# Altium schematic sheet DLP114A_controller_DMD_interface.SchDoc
size 431 x 558 mm; Date: Not shown in title block; ApprovedBy: Not shown in title block; CheckedBy: Not shown in title block; Author: Not shown in title block; CompanyName: Not shown in title block; Engineer: Not shown in title block; Organization: Not shown in title block; Address1: Not shown in title block; Address2: Not shown in title block; Address3: Not shown in title block; Address4: Not shown in title block; DocumentNumber: 7; Revision: Use project parameter SCH_Rev; SheetNumber: 7; SheetTotal: 7; PageSetup: Record=PageOptions¦CenterHorizontal=True¦CenterVertical=True¦PrintScale=1.00¦XCorrection=1.00¦YCorrection=1.00¦PrintKind=0¦BorderSize=5000000¦LeftOffset=0¦BottomOffset=0¦Orientation=2¦PaperLength=1000¦PaperWidth=1000¦Scale=100¦PaperSource=15¦PrintQuality=600¦MediaType=1¦DitherType=10¦PaperKind=Letter¦PrintScaleMode=1
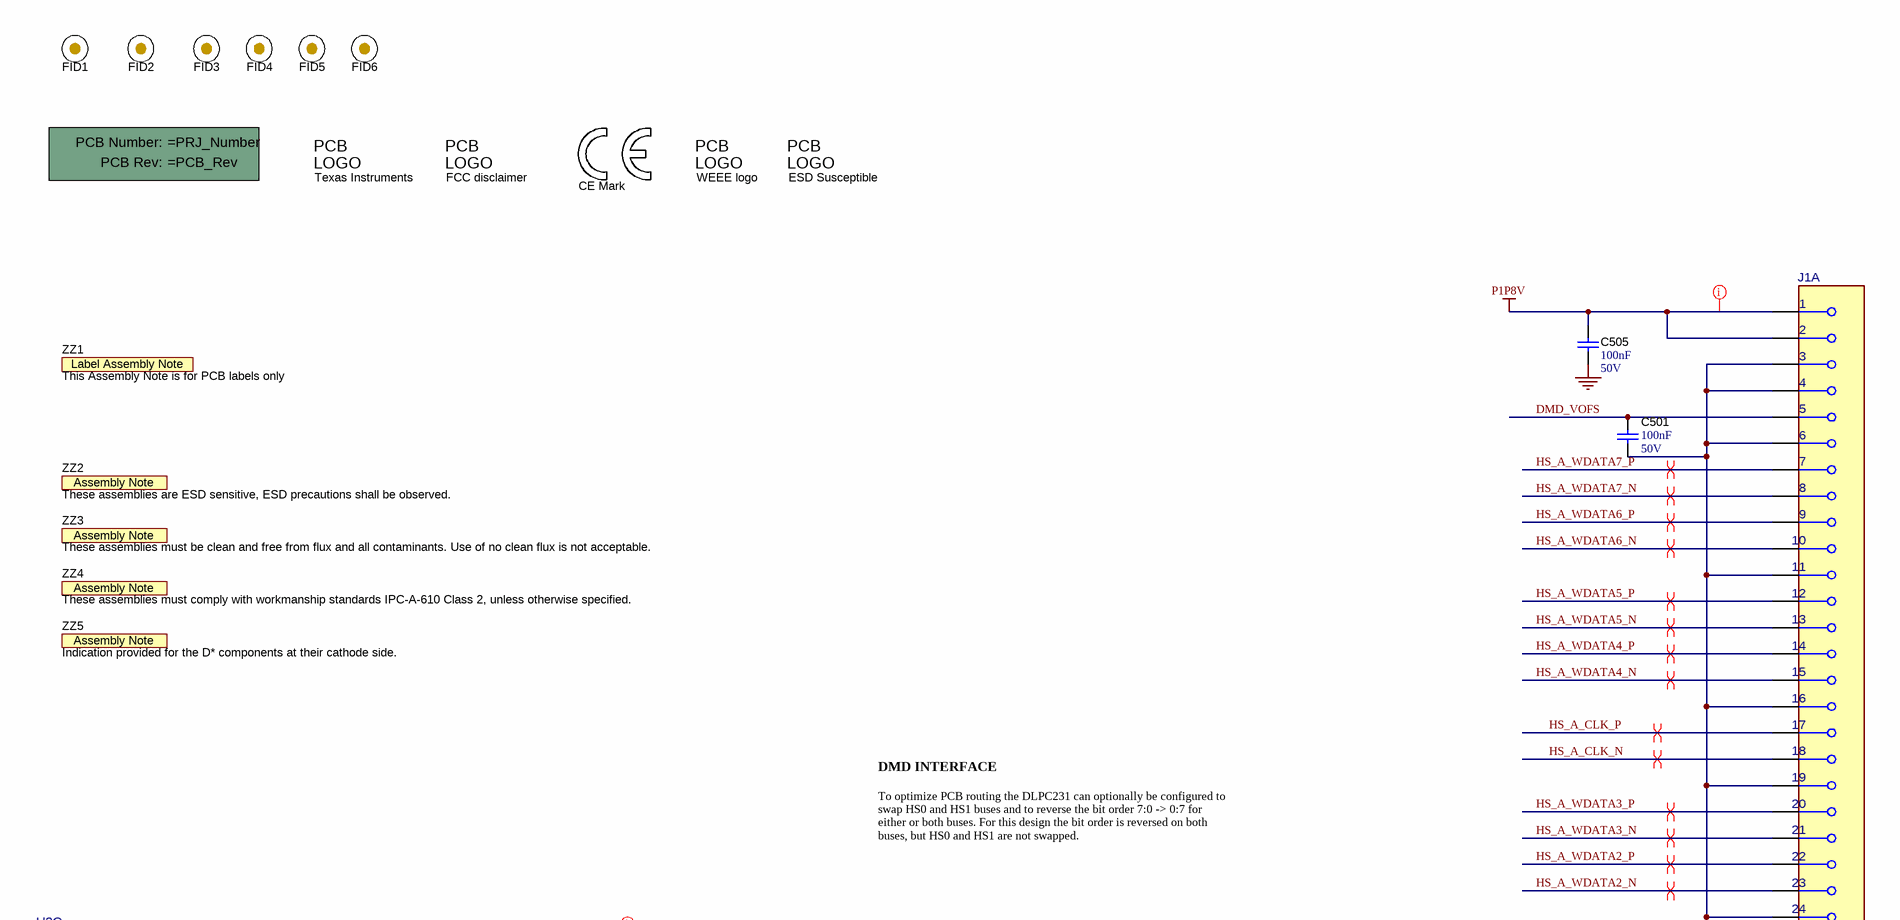
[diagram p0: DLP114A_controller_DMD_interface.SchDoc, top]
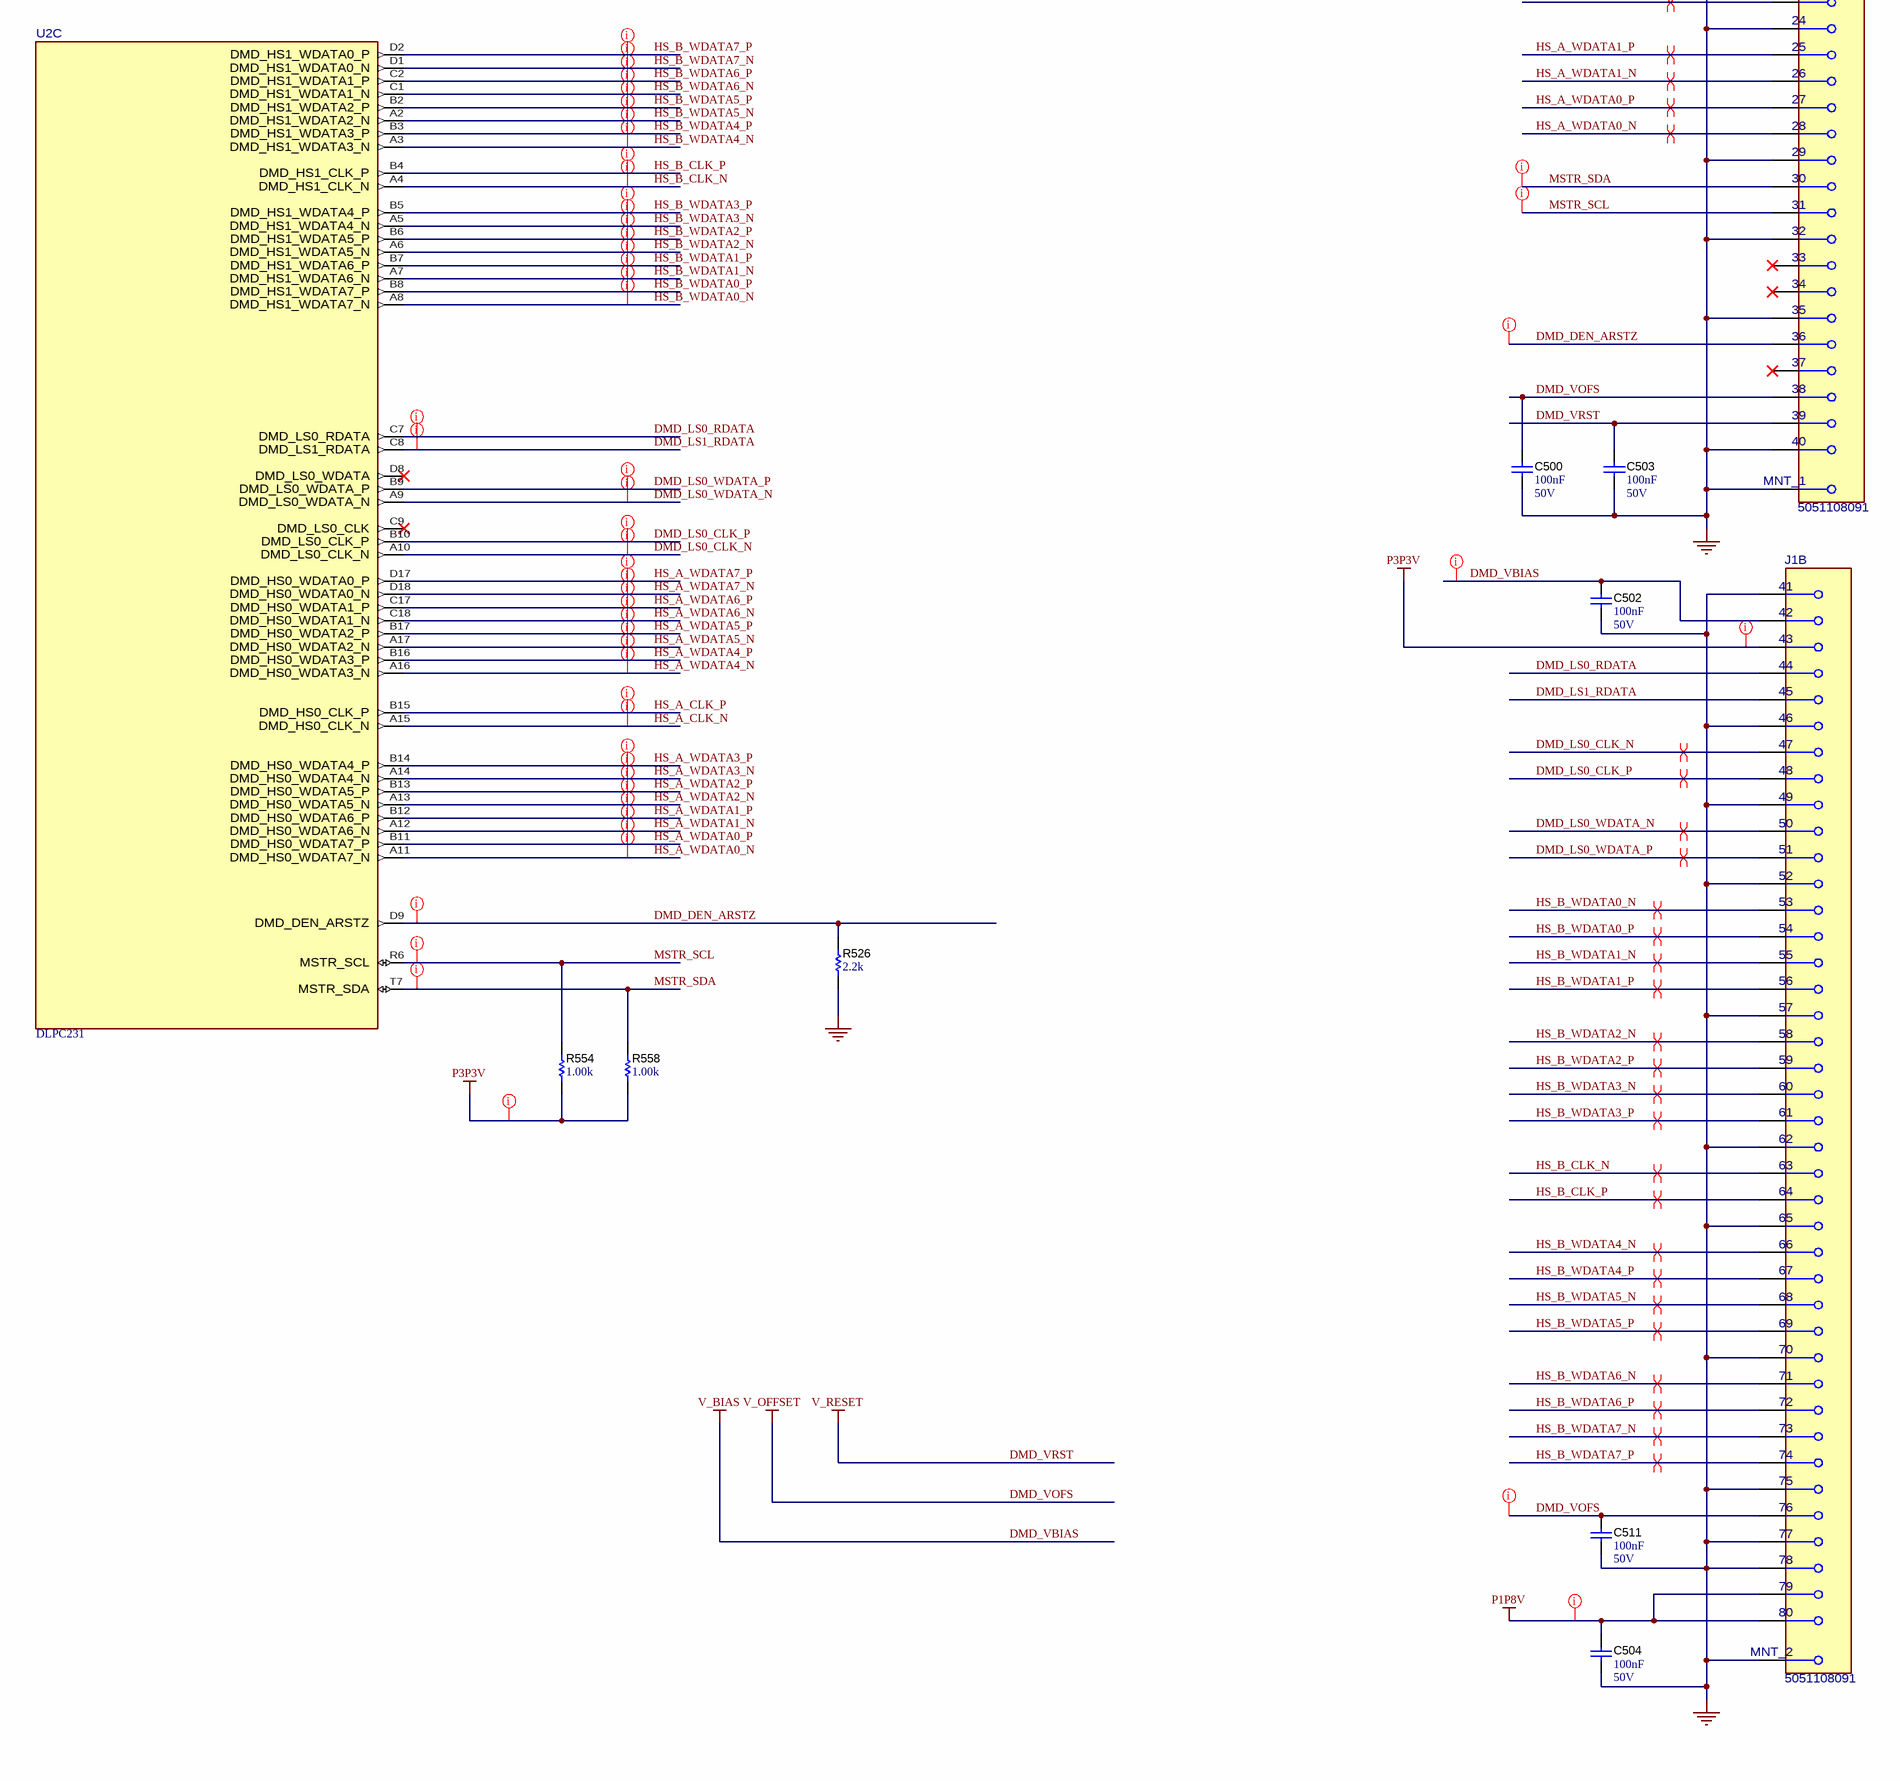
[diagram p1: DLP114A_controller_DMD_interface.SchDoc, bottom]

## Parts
!PCB1  Printed Circuit Board  (value not drawn)  (mechanical)
C500  Cap_F: 100nF  VDC_V: 50V  [0603]  (hidden comment: 06035C104KAZ2A)
C501  Cap_F: 100nF  VDC_V: 50V  [0603]  (hidden comment: 06035C104KAZ2A)
C502  Cap_F: 100nF  VDC_V: 50V  [0603]  (hidden comment: 06035C104KAZ2A)
C503  Cap_F: 100nF  VDC_V: 50V  [0603]  (hidden comment: 06035C104KAZ2A)
C504  Cap_F: 100nF  VDC_V: 50V  [0603]  (hidden comment: 06035C104KAZ2A)
C505  Cap_F: 100nF  VDC_V: 50V  [0603]  (hidden comment: 06035C104KAZ2A)
C511  Cap_F: 100nF  VDC_V: 50V  [0603]  (hidden comment: 06035C104KAZ2A)
ESD_Susceptible1  ESD Susceptible  [ESD_Overlay_Small]  (no BOM)
FID1  Fiducial  [Fiducial10-20]  (value not drawn)
FID2  Fiducial  [Fiducial10-20]  (value not drawn)
FID3  Fiducial  [Fiducial10-20]  (value not drawn)
FID4  Fiducial  [Fiducial10-20]  (value not drawn)
FID5  Fiducial  [Fiducial10-20]  (value not drawn)
FID6  Fiducial  [Fiducial10-20]  (value not drawn)
J1  5051108091  [FP-5051108091_CONN_FFC_FPC_80-MFG]  (parts A,B of 2)
Logo1  Texas Instruments  [TI_Stacked_Overlay_Small]  (no BOM)
Logo2  FCC disclaimer  [FCC_disclaimer]  (no BOM)
Logo3  CE Mark  [CE_Mark_5mm]  (no BOM)
Logo4  WEEE logo  [WEEE_Minimum]  (no BOM)
R526  ValueDisplayed: 2.2k  [0402]  (hidden comment: CRCW04022K20JNED)
R554  ValueDisplayed: 1.00k  [0402]  (hidden comment: CRCW04021K00FKED)
R558  ValueDisplayed: 1.00k  [0402]  (hidden comment: CRCW04021K00FKED)
U2  DLPC231  [ZEK0324A-MFG]  (part C of 9)
ZZ1  This Assembly Note is for PCB labels only  [AssemblyNoteLabel]  (no BOM)
ZZ2  These assemblies are ESD sensitive, ESD precautions shall be observed.  [AssemblyNote]  (no BOM)
ZZ3  These assemblies must be clean and free from flux and all contaminants. Use of no clean flux is not acceptable.  [AssemblyNote]  (no BOM)
ZZ4  These assemblies must comply with workmanship standards IPC-A-610 Class 2, unless otherwise specified.  [AssemblyNote]  (no BOM)
ZZ5  Indication provided for the D* components at their cathode side.  [AssemblyNote]  (no BOM)

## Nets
DMD_VBIAS: C502.1 J1.42  [also labelled V_BIAS]
DMD_VOFS: C500.1 C501.2 C511.1 J1.5 J1.38 J1.76  [also labelled V_OFFSET]
DMD_VRST: C503.1 J1.39  [also labelled V_RESET]
GND: C500.2 C501.1 C502.2 C503.2 C504.2 C505.2 C511.2 J1.3 J1.4 J1.6 J1.11 J1.16 J1.19 J1.24 J1.29 J1.32 J1.35 J1.40 J1.41 J1.46 J1.49 J1.52 J1.57 J1.62 J1.65 J1.70 J1.75 J1.77 J1.78 J1.81(MNT_1) J1.82(MNT_2) R526.1
P1P8V: C504.1 C505.1 J1.1 J1.2 J1.79 J1.80
P3P3V: J1.43 R554.1 R558.1
DMD_DEN_ARSTZ: J1.36 R526.2 U2.D9(DMD_DEN_ARSTZ)
DMD_LS0_CLK_N: J1.47 U2.A10(DMD_LS0_CLK_N)
DMD_LS0_CLK_P: J1.48 U2.B10(DMD_LS0_CLK_P)
DMD_LS0_RDATA: J1.44 U2.C7(DMD_LS0_RDATA)
DMD_LS0_WDATA_N: J1.50 U2.A9(DMD_LS0_WDATA_N)
DMD_LS0_WDATA_P: J1.51 U2.B9(DMD_LS0_WDATA_P)
DMD_LS1_RDATA: J1.45 U2.C8(DMD_LS1_RDATA)
HS_A_CLK_N: J1.18 U2.A15(DMD_HS0_CLK_N)
HS_A_CLK_P: J1.17 U2.B15(DMD_HS0_CLK_P)
HS_A_WDATA0_N: J1.28 U2.A11(DMD_HS0_WDATA7_N)
HS_A_WDATA0_P: J1.27 U2.B11(DMD_HS0_WDATA7_P)
HS_A_WDATA1_N: J1.26 U2.A12(DMD_HS0_WDATA6_N)
HS_A_WDATA1_P: J1.25 U2.B12(DMD_HS0_WDATA6_P)
HS_A_WDATA2_N: J1.23 U2.A13(DMD_HS0_WDATA5_N)
HS_A_WDATA2_P: J1.22 U2.B13(DMD_HS0_WDATA5_P)
HS_A_WDATA3_N: J1.21 U2.A14(DMD_HS0_WDATA4_N)
HS_A_WDATA3_P: J1.20 U2.B14(DMD_HS0_WDATA4_P)
HS_A_WDATA4_N: J1.15 U2.A16(DMD_HS0_WDATA3_N)
HS_A_WDATA4_P: J1.14 U2.B16(DMD_HS0_WDATA3_P)
HS_A_WDATA5_N: J1.13 U2.A17(DMD_HS0_WDATA2_N)
HS_A_WDATA5_P: J1.12 U2.B17(DMD_HS0_WDATA2_P)
HS_A_WDATA6_N: J1.10 U2.C18(DMD_HS0_WDATA1_N)
HS_A_WDATA6_P: J1.9 U2.C17(DMD_HS0_WDATA1_P)
HS_A_WDATA7_N: J1.8 U2.D18(DMD_HS0_WDATA0_N)
HS_A_WDATA7_P: J1.7 U2.D17(DMD_HS0_WDATA0_P)
HS_B_CLK_N: J1.63 U2.A4(DMD_HS1_CLK_N)
HS_B_CLK_P: J1.64 U2.B4(DMD_HS1_CLK_P)
HS_B_WDATA0_N: J1.53 U2.A8(DMD_HS1_WDATA7_N)
HS_B_WDATA0_P: J1.54 U2.B8(DMD_HS1_WDATA7_P)
HS_B_WDATA1_N: J1.55 U2.A7(DMD_HS1_WDATA6_N)
HS_B_WDATA1_P: J1.56 U2.B7(DMD_HS1_WDATA6_P)
HS_B_WDATA2_N: J1.58 U2.A6(DMD_HS1_WDATA5_N)
HS_B_WDATA2_P: J1.59 U2.B6(DMD_HS1_WDATA5_P)
HS_B_WDATA3_N: J1.60 U2.A5(DMD_HS1_WDATA4_N)
HS_B_WDATA3_P: J1.61 U2.B5(DMD_HS1_WDATA4_P)
HS_B_WDATA4_N: J1.66 U2.A3(DMD_HS1_WDATA3_N)
HS_B_WDATA4_P: J1.67 U2.B3(DMD_HS1_WDATA3_P)
HS_B_WDATA5_N: J1.68 U2.A2(DMD_HS1_WDATA2_N)
HS_B_WDATA5_P: J1.69 U2.B2(DMD_HS1_WDATA2_P)
HS_B_WDATA6_N: J1.71 U2.C1(DMD_HS1_WDATA1_N)
HS_B_WDATA6_P: J1.72 U2.C2(DMD_HS1_WDATA1_P)
HS_B_WDATA7_N: J1.73 U2.D1(DMD_HS1_WDATA0_N)
HS_B_WDATA7_P: J1.74 U2.D2(DMD_HS1_WDATA0_P)
MSTR_SCL: J1.31 R554.2 U2.R6(MSTR_SCL)
MSTR_SDA: J1.30 R558.2 U2.T7(MSTR_SDA)

Not connected (* = marked no-connect by the designer): J1 33* 34* 37*; U2 C9(DMD_LS0_CLK)* D8(DMD_LS0_WDATA)*

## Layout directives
net class 50OHM: DMD_DEN_ARSTZ, DMD_LS0_RDATA, DMD_LS1_RDATA, MSTR_SCL, MSTR_SDA
net class POWER: P1P8V, P3P3V
net class 100 OHM (DMD High Speed sub-LVDS): DMD_LS0_CLK_N, DMD_LS0_CLK_P, DMD_LS0_WDATA_N, DMD_LS0_WDATA_P, HS_A_CLK_N, HS_A_CLK_P, HS_A_WDATA0_N, HS_A_WDATA0_P, HS_A_WDATA1_N, HS_A_WDATA1_P, HS_A_WDATA2_N, HS_A_WDATA2_P, HS_A_WDATA3_N, HS_A_WDATA3_P, HS_A_WDATA4_N, HS_A_WDATA4_P, HS_A_WDATA5_N, HS_A_WDATA5_P, HS_A_WDATA6_N, HS_A_WDATA6_P, HS_A_WDATA7_N, HS_A_WDATA7_P, HS_B_CLK_N, HS_B_CLK_P, HS_B_WDATA0_N, HS_B_WDATA0_P, HS_B_WDATA1_N, HS_B_WDATA1_P, HS_B_WDATA2_N, HS_B_WDATA2_P, HS_B_WDATA3_N, HS_B_WDATA3_P, HS_B_WDATA4_N, HS_B_WDATA4_P, HS_B_WDATA5_N, HS_B_WDATA5_P, HS_B_WDATA6_N, HS_B_WDATA6_P, HS_B_WDATA7_N, HS_B_WDATA7_P
differential pair; differential pair class 100 OHM (DMD High Speed sub-LVDS): DMD_LS0_CLK_N, DMD_LS0_CLK_P, DMD_LS0_WDATA_N, DMD_LS0_WDATA_P, HS_A_CLK_N, HS_A_CLK_P, HS_A_WDATA0_N, HS_A_WDATA0_P, HS_A_WDATA1_N, HS_A_WDATA1_P, HS_A_WDATA2_N, HS_A_WDATA2_P, HS_A_WDATA3_N, HS_A_WDATA3_P, HS_A_WDATA4_N, HS_A_WDATA4_P, HS_A_WDATA5_N, HS_A_WDATA5_P, HS_A_WDATA6_N, HS_A_WDATA6_P, HS_A_WDATA7_N, HS_A_WDATA7_P, HS_B_CLK_N, HS_B_CLK_P, HS_B_WDATA0_N, HS_B_WDATA0_P, HS_B_WDATA1_N, HS_B_WDATA1_P, HS_B_WDATA2_N, HS_B_WDATA2_P, HS_B_WDATA3_N, HS_B_WDATA3_P, HS_B_WDATA4_N, HS_B_WDATA4_P, HS_B_WDATA5_N, HS_B_WDATA5_P, HS_B_WDATA6_N, HS_B_WDATA6_P, HS_B_WDATA7_N, HS_B_WDATA7_P
net class Voltage Spacing (15Mils): DMD_VBIAS, DMD_VOFS

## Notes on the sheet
- DMD INTERFACE
- To optimize PCB routing the DLPC231 can optionally be configured to
  swap HS0 and HS1 buses and to reverse the bit order 7:0 -> 0:7 for
  either or both buses. For this design the bit order is reversed on both
  buses, but HS0 and HS1 are not swapped.

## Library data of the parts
!PCB1 = CMP-0003618-2: Manufacturer: Any
C500-C505 C511 = CMP-0079095-1: CAP, CERM, 0.1 µF, 50 V,+/- 10%, X7R, AEC-Q200 Grade 1, 0603; Manufacturer: AVX; SizeAreaWB_mm2: 4.68; SizeArea_mm2: 1.28; AEC Qualified: Y; AEC Category: Q200; Value: 0.1uF; TaMax_C: 125°C; SizeZ_mm: 1; Polarized: N; TaMin_C: -55°C; SizeY_mm: 0.8; U/M: EA; SizeX_mm: 1.6; ValueDisplayed: 0.1µF
ESD_Susceptible1 = CMP-0074840-1: ESD Susceptible Symbol; Library Reference: Logo; SymbolCreator: a0412235; Lib Reference: ESD_Susceptible
FID1-FID6 = CMP-0077181-1: Fiducial mark.  There is nothing to buy or mount.
J1 = CMP-0095889-1: 80 Position FFC, FPC Connector Contacts, Bottom 0.020" (0.50mm) Surface Mount, Right Angle; Manufacturer: Molex; AEC Qualified: No; SizeZ_mm: 4.26mm; Is Female: yes; Current_A: 500mA; ContactFinish: Gold,Nickel; Voltage_V: 50V; DUT-Pitch_mm: 0.5mm; Conn Gender: Female
Logo1 = CMP-0074838-1: Texas Instrument Corporate Signature; SymbolCreator: a0412235; Lib Reference: TI_Logo; Library Reference: Logo
Logo2 = CMP-0074847-1: FCC_disclaimer; Library Reference: Logo
Logo3 = CMP-0074844-1: SymbolCreator: a0412235
Logo4 = CMP-0074769-1
R526 = CMP-0026890-5: RES, 2.2 k, 5%, 0.063 W, AEC-Q200 Grade 0, 0402; Manufacturer: Vishay-Dale; Power_W: 63mW; TempCo: 200 ppm/C; Value_Code: 2k20; Value: 2.2k; EIA_Code: E24; SizeX_mm: 1; SizeY_mm: 0.5; SizeZ_mm: 0.6; Value2: 0.063W; AEC Qualified: Y; VDC_V: 50V; AEC Category: Q200; AEC Grade: 0
R554 R558 = CMP-0026071-3: RES, 1.00 k, 1%, 0.063 W, AEC-Q200 Grade 0, 0402; Manufacturer: Vishay-Dale; Power_W: 63mW; TempCo: 100 ppm/C; Value_Code: 1k00; Value: 1.00k; EIA_Code: E96; Res_ohm: 1k; SizeX_mm: 1; SizeY_mm: 0.5; SizeZ_mm: 0.6; Value2: 0.063W; AEC Qualified: Y; VDC_V: 50V; AEC Category: Q200; AEC Grade: 0
U2 = CMP-0096130-1: Manufacturer: Texas Instruments; Standoff Height: 0.35mm; SizeZ_mm: 1.5mm
ZZ1 = CMP-0003616-3
ZZ2 = CMP-0077236-1
ZZ3 = CMP-0077237-1
ZZ4 ZZ5 = CMP-0077238-1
